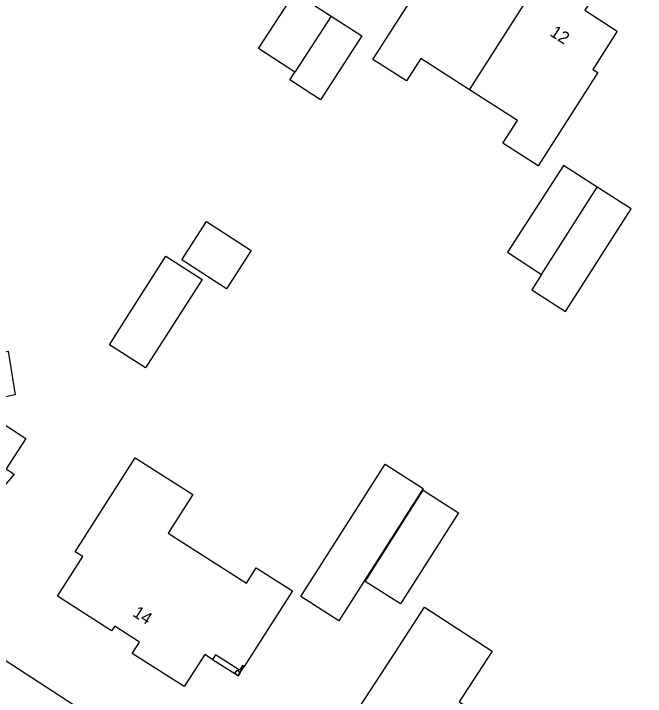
# Model space of a CAD drawing. Extents: x 161141 to 161601, y 381708 to 382245.
# Drawn here: x 161326.4 to 161378, y 381968.7 to 382024.5 of the extents above; entities that cross this region are included whole.
import ezdxf

# ---------------------------------------------------------------- set-up
doc = ezdxf.new("R2010")
doc.units = 0
for name, color, linetype in [('IMGEO_Pand', 7, 'Continuous'), ('IMGEO_Pand_nummerreeks', 7, 'Continuous'), ('IMGEO_Pand_overbouw', 7, 'Continuous'), ('IMGEO_Voetpad_open', 7, 'Continuous')]:
    doc.layers.add(name, color=color, linetype=linetype)

msp = doc.modelspace()

# ---------------------------------------------------------------- linework, layer by layer
at = {"layer": 'IMGEO_Pand'}
for points in [[(161363.651, 382018.259), (161359.669, 382020.808), (161358.499, 382018.98), (161355.762, 382020.732), (161357.956, 382024.159), (161360.651, 382028.37), (161361.044, 382028.118), (161363.016, 382031.198), (161365.6, 382029.544), (161366.437, 382030.853), (161370.18, 382028.457)], [(161370.18, 382028.457), (161373.925, 382026.06), (161373.085, 382024.748), (161375.732, 382023.053), (161373.728, 382019.922), (161374.141, 382019.658), (161371.446, 382015.447), (161369.264, 382012.038), (161366.393, 382013.876), (161367.587, 382015.74), (161363.651, 382018.259)], [(161363.651, 382018.259), (161370.18, 382028.457)], [(161349.384, 382019.699), (161346.418, 382021.618), (161349.381, 382026.197), (161352.347, 382024.278)], [(161352.347, 382024.278), (161354.854, 382022.657), (161351.48, 382017.438), (161348.971, 382019.06), (161349.384, 382019.699)], [(161352.347, 382024.278), (161349.384, 382019.699)], [(161374.103, 382010.292), (161371.341, 382012.053), (161366.763, 382004.969), (161369.553, 382003.166)], [(161369.553, 382003.166), (161368.738, 382001.908), (161371.513, 382000.138), (161376.865, 382008.53), (161374.103, 382010.292)], [(161369.553, 382003.166), (161374.103, 382010.292)], [(161343.792, 382001.991), (161340.135, 382004.348), (161342.156, 382007.484), (161345.814, 382005.126), (161343.792, 382001.991)], [(161337.186, 381995.52), (161334.228, 381997.409), (161335.883, 382000), (161338.848, 382004.642), (161341.806, 382002.753), (161337.186, 381995.52)], [(161322.733, 381996.437), (161323.014, 381996.257), (161325.944, 381996.899), (161326.519, 381993.307), (161323.584, 381992.685), (161323.366, 381992.35), (161327.411, 381989.759), (161325.791, 381987.268), (161326.455, 381986.845), (161323.779, 381983.735), (161323.17, 381984.124), (161321.429, 381981.396), (161319.905, 381982.369), (161319.684, 381982.022), (161318.379, 381982.855), (161318.642, 381983.266), (161315.516, 381985.262)], [(161345.229, 381971.099), (161345.094, 381971.185), (161344.863, 381970.822), (161342.904, 381972.07), (161342.662, 381971.691), (161342.021, 381972.099), (161340.338, 381969.467), (161336.1, 381972.176), (161336.689, 381973.098), (161334.659, 381974.396), (161334.413, 381974.038), (161329.982, 381976.855), (161332.06, 381980.096), (161331.431, 381980.495), (161336.33, 381988.176), (161341.044, 381985.169), (161339.024, 381982.002), (161345.419, 381977.923), (161346.226, 381979.188), (161349.184, 381977.301), (161345.229, 381971.099)], [(161352.976, 381974.835), (161349.863, 381976.821), (161356.765, 381987.643), (161359.878, 381985.658), (161352.976, 381974.835)], [(161358.01, 381976.224), (161355.121, 381978.069), (161359.879, 381985.518), (161362.768, 381983.673), (161358.01, 381976.224)], [(161359.985, 381975.96), (161365.513, 381972.374), (161362.821, 381968.223), (161366.916, 381965.576), (161363.429, 381960.199), (161360.708, 381956.003), (161351.088, 381962.243), (161353.809, 381966.438), (161357.287, 381971.8), (161359.985, 381975.96)], [(161344.756, 381970.357), (161344.621, 381970.443), (161344.486, 381970.529), (161344.658, 381970.798), (161344.928, 381970.626), (161344.756, 381970.357)]]:
    msp.add_lwpolyline(points, dxfattribs=at)
at = {"layer": 'IMGEO_Pand_overbouw'}
msp.add_lwpolyline([(161342.662, 381971.691), (161344.486, 381970.529), (161344.621, 381970.443), (161344.756, 381970.357), (161344.928, 381970.626), (161345.229, 381971.099), (161345.094, 381971.185), (161344.863, 381970.822), (161342.904, 381972.07)], close=True, dxfattribs=at)
at = {"layer": 'IMGEO_Voetpad_open'}
msp.add_lwpolyline([(161278.294, 382002.287), (161281.877, 382000), (161299.823, 381988.353), (161310.674, 381981.109), (161322.611, 381973.432), (161322.712, 381973.551), (161378.924, 381936.994), (161385.641, 381932.206), (161392.817, 381926.552), (161429.313, 381896.994)], dxfattribs=at)

# ---------------------------------------------------------------- texts
at = {"layer": 'IMGEO_Pand_nummerreeks'}
for s, rotation, p in [('12', 327.3591, (161370.162, 382022.725)), ('14', 327.4044, (161336.056, 381975.284))]:
    msp.add_text(s, height=1, rotation=rotation, dxfattribs=at).set_placement(p)

doc.saveas('drawing.dxf')
